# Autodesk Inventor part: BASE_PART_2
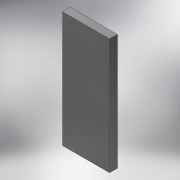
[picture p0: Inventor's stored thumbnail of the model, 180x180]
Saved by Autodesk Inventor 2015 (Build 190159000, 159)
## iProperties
Created: 2014-08
Part Number: BASE_PART_2
Material: Steel, Mild
Document SubType Name: Modeling
Designer: lakshayg
Density: 7.85 g/cm^3
Appearance: Semi-Polished
Mass: 1205.91 g
Surface Area: 315.984 cm^2
Volume: 153.619 cm^3
Author: lakshayg
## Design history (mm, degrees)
sketch "Sketch1"
  geometry: L1 (0, 0)-(-72, 0); L2 (-72, 0)-(-72, -177.8); L3 (-72, -177.8)-(0, -177.8); L4 (0, -177.8)-(0, 0)
  constraints: 8 end point, 2 parallel, 1 horizontal, 1 perpendicular
  dimensions: "d0" = 177.8 distance of L3.end L1.start; "d1" = 72 distance of L1.start L1.end
extrude "Extrusion1" new body sketch "Sketch1" distance "d2" = 12; taper "d3" = 0 deg
body "Solid1"
